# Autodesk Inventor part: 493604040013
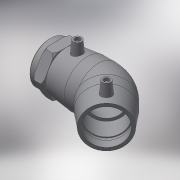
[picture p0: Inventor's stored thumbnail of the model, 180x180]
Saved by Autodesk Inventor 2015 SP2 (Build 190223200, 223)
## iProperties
Created: 2017-06
Part Number: 493604040013
Material: Generic
Description: PLASSON 45° ELBOW TRANSITION FEMALE 40-1.1/4"
Document SubType Name: Modeling
Designer: KIM
Mass: 176.119 g
Surface Area: 459.407 cm^2
Volume: 176.119 cm^3
Density: 1 g/cm^3
Appearance: Default
Author: KIM
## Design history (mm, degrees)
derived "493604.ipt"
feature "Solid1::493604.ipt"
tag "TaggingFeature1"
body "Solid1"
other parameters: "d2" = 56, "d4" = 27, "d5" = 50.4, "d8" = 168 deg, "d10" = 17.6, "d11" = 5.86667, "d29" = 47, "d30" = 15, "d31" = 37.8, "d34" = 5 deg, "d41" = 4, "d42" = 14, "d43" = 0, "d50" = 34, "d51" = 17.6, "d52" = 44, "d54" = 135 deg, "d86" = 25.2, "d87" = 135 deg, "d88" = 108, "d90" = 44, "d91" = 0, "d92" = 44, "d93" = 0, "d101" = 3, "d102" = 0, "d107" = 0.1, "d108" = 29, "d110" = 25, "d112" = 50.4, "d113" = 38.952, "d114" = 22.5, "d128" = 15, "d129" = 0, "d132" = 2, "d133" = 45 deg, "d134" = 45 deg, "d136" = 1.2, "L_" = 133, "L_1" = 44, "D_" = 29, "A_" = 47, "d_2" = 12, "L_2" = 25, "Rp_" = 38.952, "D_1" = 56
